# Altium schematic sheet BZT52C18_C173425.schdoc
size 127 x 101 mm
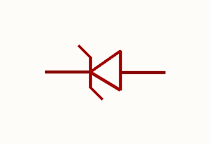
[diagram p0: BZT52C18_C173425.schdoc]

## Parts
D?  bzt52c18_c173425  [SOD-123_L2.8-W1.8-LS3.7-RD]  (value not drawn)

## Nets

Not connected (* = marked no-connect by the designer): D? 1 2

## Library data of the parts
D? = bzt52c18_c173425: 二极管配置:1个独立式;稳压值(标称值):18V;稳压值(范围):17.1V~18.9V;耗散功率(Pd):500mW;; Manufacturer: MDD(辰达半导体); AddInBom: yes; ModelId: 7884390a25fb4c08947731ebfba7e3f8; ModelTransform: 144.8816,62.992,0,0,0,0,0,0,0; Diode Configuration: 1个独立式; Zener Voltage(Nom): 18V; Reverse Leakage Current (Ir): 100nA@13V; Pd - Power Dissipation: 500mW; Impedance(Zzt): 45Ω; Tolerance: ±5%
